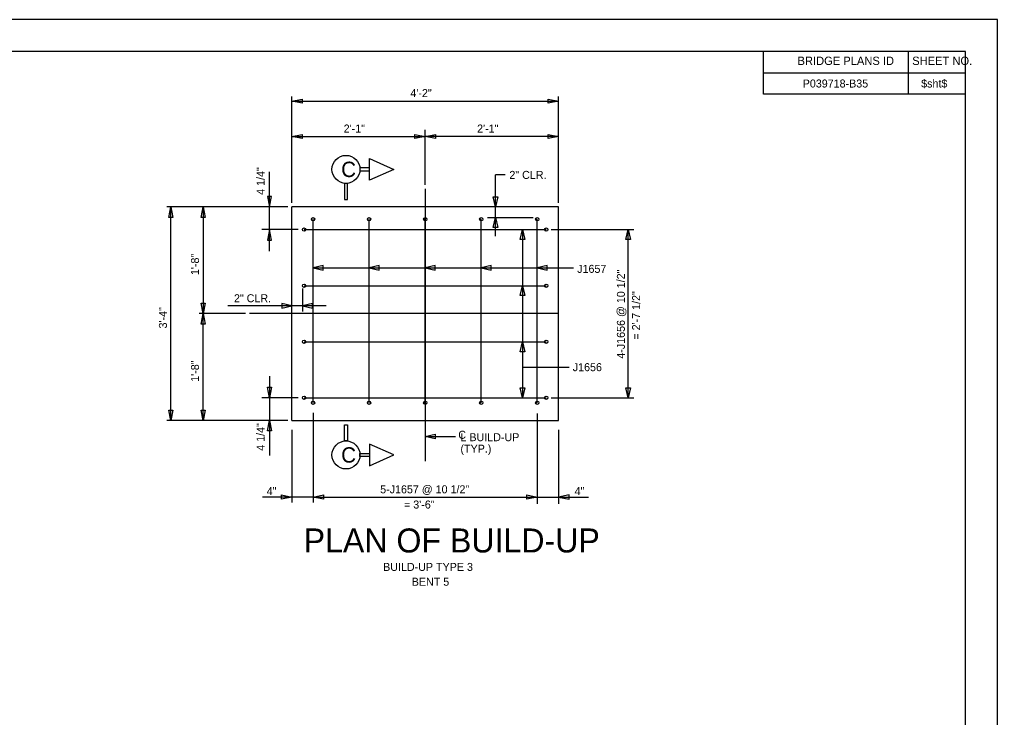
# Model space of a CAD drawing. Extents: x -133.1 to -97, y -1.7 to 20.3.
# Drawn here: x -112.41 to -97.14, y 9.41 to 20.31 of the extents above; entities that cross this region are included whole.
import ezdxf

# ---------------------------------------------------------------- set-up
doc = ezdxf.new("R2010")
doc.units = 0
for name, color, linetype in [('BR_AUTO DIMENSION', 7, 'Continuous'), ('BR_BORDER LINES', 7, 'Continuous'), ('BR_CENTER LINES', 7, 'Continuous'), ('BR_CONCRETE', 7, 'Continuous'), ('BR_REBAR', 7, 'Continuous'), ('BR_TEXT', 7, 'Continuous'), ('Level 31', 7, 'Continuous')]:
    doc.layers.add(name, color=color, linetype=linetype)

msp = doc.modelspace()

# ---------------------------------------------------------------- linework, layer by layer
at = {"layer": 'BR_AUTO DIMENSION'}
for p, q in [((-108.162, 17.446), (-108.162, 19.11)), ((-103.995, 17.446), (-103.995, 19.11)), ((-108.162, 19.036), (-103.995, 19.036)), ((-108.162, 18.482), (-106.078, 18.482)), ((-106.078, 17.73), (-106.078, 18.587)), ((-103.995, 18.482), (-106.078, 18.482)), ((-108.509, 16.693), (-108.509, 17.931)), ((-104.982, 16.929), (-104.982, 17.884)), ((-104.829, 17.884), (-104.982, 17.884)), ((-108.224, 17.383), (-110.111, 17.383)), ((-110.048, 14.05), (-110.048, 17.383)), ((-109.547, 17.383), (-109.547, 15.717)), ((-105.104, 17.217), (-104.392, 17.217)), ((-108.061, 17.029), (-108.628, 17.029)), ((-104.557, 17.029), (-104.557, 14.404)), ((-104.11, 17.029), (-102.818, 17.029)), ((-102.91, 14.404), (-102.91, 17.029)), ((-107.828, 16.432), (-103.763, 16.432)), ((-107.995, 16.109), (-107.995, 15.753)), ((-107.622, 15.838), (-109.161, 15.838)), ((-108.885, 15.717), (-109.61, 15.717)), ((-109.547, 14.05), (-109.547, 15.717)), ((-104.557, 14.884), (-103.829, 14.884)), ((-108.509, 14.74), (-108.509, 13.502)), ((-108.061, 14.404), (-108.628, 14.404)), ((-104.11, 14.404), (-102.818, 14.404)), ((-107.828, 14.167), (-107.828, 12.769)), ((-104.328, 14.157), (-104.328, 12.748)), ((-108.224, 14.05), (-110.111, 14.05)), ((-108.162, 13.905), (-108.162, 12.769)), ((-103.995, 13.905), (-103.995, 12.748)), ((-106.078, 13.799), (-105.607, 13.799)), ((-107.828, 12.854), (-108.621, 12.854)), ((-107.828, 12.854), (-104.328, 12.854)), ((-104.328, 12.854), (-103.527, 12.854))]:
    msp.add_line(p, q, dxfattribs=at)
for points in [[(-107.999, 19.005), (-108.162, 19.036), (-107.999, 19.068)], [(-104.157, 19.068), (-103.995, 19.036), (-104.157, 19.005)], [(-107.999, 18.451), (-108.162, 18.482), (-107.999, 18.514)], [(-106.241, 18.514), (-106.078, 18.482), (-106.241, 18.451)], [(-105.916, 18.451), (-106.078, 18.482), (-105.916, 18.514)], [(-104.157, 18.514), (-103.995, 18.482), (-104.157, 18.451)], [(-108.541, 17.546), (-108.509, 17.383), (-108.478, 17.546)], [(-104.946, 17.539), (-104.982, 17.383), (-105.018, 17.539)], [(-110.079, 17.221), (-110.048, 17.383), (-110.017, 17.221)], [(-109.578, 17.221), (-109.547, 17.383), (-109.516, 17.221)], [(-105.018, 17.061), (-104.982, 17.217), (-104.946, 17.061)], [(-108.478, 16.867), (-108.509, 17.029), (-108.541, 16.867)], [(-104.593, 16.873), (-104.557, 17.029), (-104.521, 16.873)], [(-102.946, 16.873), (-102.91, 17.029), (-102.874, 16.873)], [(-107.672, 16.468), (-107.828, 16.432), (-107.672, 16.396)], [(-106.797, 16.468), (-106.953, 16.432), (-106.797, 16.396)], [(-105.922, 16.468), (-106.078, 16.432), (-105.922, 16.396)], [(-105.047, 16.468), (-105.203, 16.432), (-105.047, 16.396)], [(-104.172, 16.468), (-104.328, 16.432), (-104.172, 16.396)], [(-104.593, 15.998), (-104.557, 16.154), (-104.521, 15.998)], [(-109.516, 15.879), (-109.547, 15.717), (-109.578, 15.879)], [(-108.318, 15.802), (-108.162, 15.838), (-108.318, 15.874)], [(-107.839, 15.874), (-107.995, 15.838), (-107.839, 15.802)], [(-109.578, 15.554), (-109.547, 15.717), (-109.516, 15.554)], [(-104.593, 15.123), (-104.557, 15.279), (-104.521, 15.123)], [(-108.478, 14.567), (-108.509, 14.404), (-108.541, 14.567)], [(-104.521, 14.56), (-104.557, 14.404), (-104.593, 14.56)], [(-102.874, 14.56), (-102.91, 14.404), (-102.946, 14.56)], [(-110.017, 14.212), (-110.048, 14.05), (-110.079, 14.212)], [(-109.516, 14.212), (-109.547, 14.05), (-109.578, 14.212)], [(-108.541, 13.887), (-108.509, 14.05), (-108.478, 13.887)], [(-105.922, 13.763), (-106.078, 13.799), (-105.922, 13.835)], [(-108.324, 12.886), (-108.162, 12.854), (-108.324, 12.823)], [(-107.666, 12.823), (-107.828, 12.854), (-107.666, 12.886)], [(-104.491, 12.886), (-104.328, 12.854), (-104.491, 12.823)], [(-103.832, 12.886), (-103.995, 12.854), (-103.832, 12.823)]]:
    msp.add_lwpolyline(points, close=True, dxfattribs=at)
at = {"layer": 'BR_BORDER LINES'}
for p, q in [((-97.642, 19.809), (-131.308, 19.809)), ((-100.794, 19.142), (-100.794, 19.809)), ((-98.528, 19.142), (-98.528, 19.809)), ((-97.642, -1.191), (-97.642, 19.809)), ((-100.794, 19.479), (-97.642, 19.479)), ((-98.528, 19.479), (-97.642, 19.479)), ((-97.642, 19.142), (-100.794, 19.142))]:
    msp.add_line(p, q, dxfattribs=at)
at = {"layer": 'BR_CENTER LINES'}
for p, q in [((-106.078, 17.667), (-106.078, 13.416)), ((-103.995, 15.717), (-108.822, 15.717))]:
    msp.add_line(p, q, dxfattribs=at)
at = {"layer": 'BR_CONCRETE'}
for p, q in [((-108.162, 14.05), (-108.162, 17.383)), ((-103.995, 17.383), (-108.162, 17.383)), ((-103.995, 14.05), (-103.995, 17.383)), ((-108.162, 14.05), (-103.995, 14.05))]:
    msp.add_line(p, q, dxfattribs=at)
at = {"layer": 'BR_REBAR'}
for p, q in [((-107.828, 14.326), (-107.828, 17.191)), ((-106.953, 14.326), (-106.953, 17.191)), ((-106.078, 14.326), (-106.078, 17.191)), ((-105.203, 14.326), (-105.203, 17.191)), ((-104.328, 14.326), (-104.328, 17.191)), ((-107.969, 17.029), (-104.188, 17.029)), ((-107.969, 16.154), (-104.188, 16.154)), ((-107.969, 15.279), (-104.188, 15.279)), ((-107.969, 14.404), (-104.188, 14.404))]:
    msp.add_line(p, q, dxfattribs=at)
for centre, radius in [((-107.828, 17.191), 0.026), ((-106.953, 17.191), 0.026), ((-106.078, 17.191), 0.026), ((-105.203, 17.191), 0.026), ((-104.328, 17.191), 0.026), ((-107.969, 17.029), 0.0261), ((-104.188, 17.029), 0.0261), ((-107.969, 16.154), 0.0261), ((-104.188, 16.154), 0.0261), ((-107.969, 15.279), 0.0261), ((-104.188, 15.279), 0.0261), ((-107.969, 14.404), 0.0261), ((-104.188, 14.404), 0.0261), ((-107.828, 14.326), 0.026), ((-106.953, 14.326), 0.026), ((-106.078, 14.326), 0.026), ((-105.203, 14.326), 0.026), ((-104.328, 14.326), 0.026)]:
    msp.add_circle(centre, radius, dxfattribs=at)
at = {"layer": 'BR_TEXT'}
for points in [[(-106.946, 18.139), (-106.57, 17.97), (-106.946, 17.801)], [(-107.096, 17.945), (-106.946, 17.945), (-106.946, 17.995), (-107.096, 17.995)], [(-107.34, 17.501), (-107.29, 17.501), (-107.29, 17.751), (-107.34, 17.751)], [(-107.34, 13.98), (-107.29, 13.98), (-107.29, 13.73), (-107.34, 13.73)], [(-106.946, 13.342), (-106.57, 13.511), (-106.946, 13.68)], [(-107.096, 13.536), (-106.946, 13.536), (-106.946, 13.486), (-107.096, 13.486)]]:
    msp.add_lwpolyline(points, close=True, dxfattribs=at)
for centre in [(-107.315, 17.97), (-107.315, 13.511)]:
    msp.add_circle(centre, 0.219, dxfattribs=at)
at = {"layer": 'Level 31'}
msp.add_lwpolyline([(-133.141, -1.691), (-97.141, -1.691), (-97.141, 20.309), (-133.141, 20.309)], close=True, dxfattribs=at)

# ---------------------------------------------------------------- texts
at = {"layer": 'BR_AUTO DIMENSION'}
for s, p in [('4\'-2"', (-106.309, 19.099)), ('2\'-1"', (-107.351, 18.545)), ('2\'-1"', (-105.267, 18.545)), ('2" CLR.', (-104.763, 17.821)), ('J1657', (-103.704, 16.354)), ('2" CLR.', (-109.064, 15.895)), ('J1656', (-103.773, 14.819)), ('C', (-105.561, 13.763)), ('L BUILD-UP', (-105.527, 13.726)), ('(TYP.)', (-105.527, 13.546)), ('4"', (-108.553, 12.883)), ('5-J1657 @ 10 1/2"', (-106.781, 12.912)), ('4"', (-103.745, 12.883)), ('= 3\'-6"', (-106.408, 12.674)), ('BUILD-UP TYPE 3', (-106.735, 11.7)), ('BENT 5', (-106.288, 11.469))]:
    msp.add_text(s, height=0.125, dxfattribs=at).set_placement(p)
for s, p in [('4 1/4"', (-108.586, 17.572)), ('1\'-8"', (-109.61, 16.319)), ('4-J1656 @ 10 1/2"', (-102.959, 15.014)), ('= 2\'-7 1/2"', (-102.721, 15.312)), ('3\'-4"', (-110.111, 15.486)), ('1\'-8"', (-109.61, 14.653)), ('4 1/4"', (-108.586, 13.576))]:
    msp.add_text(s, height=0.125, rotation=90, dxfattribs=at).set_placement(p)
at = {"layer": 'BR_TEXT'}
for s, height, p in [('BRIDGE PLANS ID', 0.13, (-100.263, 19.6)), ('SHEET NO.', 0.13, (-98.472, 19.6)), ('P039718-B35', 0.125, (-100.182, 19.248)), ('$sht$', 0.125, (-98.332, 19.248)), ('C', 0.24, (-107.39, 17.85)), ('C', 0.24, (-107.39, 13.391)), ('PLAN OF BUILD-UP', 0.375, (-107.976, 11.988))]:
    msp.add_text(s, height=height, dxfattribs=at).set_placement(p)

doc.saveas('drawing.dxf')
